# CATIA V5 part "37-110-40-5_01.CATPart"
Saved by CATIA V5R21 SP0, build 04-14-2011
Part number: 37-110-40-5_01
Bounding box of the stored display mesh (mm): x -2 to 2, y 3.5 to 7.7, z -18 to 18
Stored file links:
  C:\Users\zerma\Pictures\Stage Stomate\37-110-40-5_01.CATPart
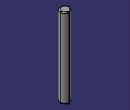
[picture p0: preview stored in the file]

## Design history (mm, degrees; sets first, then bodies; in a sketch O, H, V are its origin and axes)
AxisSystem1: origin (0, 0, 0), X (1, 0, 0), Y (0, 1, 0), Z (0, 0, 1)
Body1 "37-110-40-5_01" (main body)
  Solid1: solid without history
  Affinity1: ToTransfor Solid1, RatioX 1, RatioY 1, RatioZ 0.9
  Sketch1 on face of Solid1, origin (0, 0, 18), H (1, 0, 0), V (0, 1, 0)
    point P1 (0, 7.7)
    reference projected line E1 (2, 5.5) -> (1.5, 5.5) from edge [face of Solid1 | face of Solid1]
    point P2 (2, 5.5)
    reference projected line E3 (2, 5.5) -> (1.5, 5.5) from edge [face of Solid1 | face of Solid1]
    line L1 (2, 5.5) -> (0, 7.7)
    point P3 (0, 7.7)
    point P4 (-2, 5.5)
    line L2 (-2, 5.5) -> (0, 7.7)
    line L3 (-2, 5.5) -> (2, 5.5)
    distance P1 E1 = 2.2
    distance P2 E3 = 0
    distance P2 V = 2
    symmetry: P1 P3 V, P2 P4 V, L1 L2 V
    horizontal: L3 H
    coincidence: P1 P3
  Pad1: profile Sketch1, direction (0, 0, -1), up to face of Solid1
